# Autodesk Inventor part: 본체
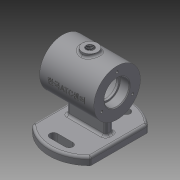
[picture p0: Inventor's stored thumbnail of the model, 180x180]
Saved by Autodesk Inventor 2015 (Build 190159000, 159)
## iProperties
Created: 2021-09
Part Number: 본체
Material: 일반
Document SubType Name: Modeling
Designer: 1019876
Density: 1 g/cm^3
Appearance: 기본값
Author: 1019876
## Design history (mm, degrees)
sketch "스케치1"
  geometry: C1 r 52.5 at (0, 0); 1 further point
  constraints: 1 centre point, 1 coincident
  dimensions: "d0" = 105 diameter of C1
extrude "돌출1" new body sketch "스케치1" distance "d1" = 10; taper "d2" = 0 deg
sketch "스케치2"
  geometry: L1 (-37.5, 36.742)-(-37.5, -36.742); L2 (37.5, 36.742)-(37.5, -36.742); A1 r 52.5 centre (0, 0) between (-37.5, 36.742) and (-37.5, -36.742) reference
  constraints: 4 end point, 4 point on circle, 2 vertical
  dimensions: "d3" = 75 distance between parallel lines of L2 L1; "d4" = 37.5 distance from line of A1.centre L1
extrude "돌출2" cut sketch "스케치2" stored distance "d5" = 10; taper "d6" = 0 deg
sketch "스케치3"
  geometry: L1 (-15, 37)-(15, 37); L2 (-10, 32)-(10, 32); L3 (10, 42)-(-10, 42); A1 r 52.5 centre (0, 0) between (-37.5, -36.742) and (37.5, -36.742) reference; A2 r 5 centre (-10, 37) between (-10, 42) and (-10, 32); A3 r 5 centre (10, 37) between (10, 32) and (10, 42); 1 further point
  constraints: 8 end point, 6 point on circle, 4 tangent, 2 centre point, 2 point on line, 1 horizontal, 1 midpoint, 1 parallel, 1 vertical alignment
  dimensions: "d7" = 20 distance of A3.centre A2.centre; "d8" = 5 distance from line of point (0, 37) L3; "d9" = 37 distance of A1.centre point (0, 37)
extrude "돌출3" cut sketch "스케치3" stored distance "d10" = 10; taper "d11" = 0 deg
sketch "스케치4"
  geometry: L1 (-37.5, 36.742)-(-37.5, -36.742) reference; L2 (-25, 5)-(25, 5); L3 (25, 5)-(25, -5); L4 (25, -5)-(-25, -5); L5 (-25, -5)-(-25, 5); A1 r 52.5 centre (0, 0) between (-37.5, -36.742) and (37.5, -36.742) reference
  constraints: 8 end point, 2 parallel, 1 horizontal, 1 perpendicular
  dimensions: "d12" = 50 distance of L3.end L4.end; "d13" = 12.5 distance between parallel lines of L5 L1; "d14" = 10 distance between parallel lines of L4 L2; "d15" = 5 distance from line of L2 A1.centre
extrude "돌출4" join sketch "스케치4" distance "d16" = 52; taper "d17" = 0 deg
sketch "스케치5"
  geometry: L1 (35, 92)-(-35, 92); L2 (-35, 92)-(-35, 62); L3 (-35, 62)-(35, 62); L4 (35, 62)-(35, 92); L5 (25, 62)-(-25, 62) reference; L6 (-37.5, 0)-(37.5, 0) reference; 3 further points
  constraints: 8 end point, 2 midpoint, 2 parallel, 1 horizontal, 1 perpendicular, 1 vertical alignment
  dimensions: "d18" = 30 distance of L3.end L1.start; "d19" = 0 distance between parallel lines of L5 L3; "d20" = 70 distance of L1.start L1.end
revolve "회전1" sketch "스케치5" stored, may be unused: angle "d21" = 90 deg
sketch "스케치6"
  geometry: C1 r 30 at (0, 0) reference; C2 r 16 at (0, 0); 1 further point
  constraints: 1 centre point, 1 coincident
  dimensions: "d22" = 32 diameter of C2
extrude "돌출5" cut sketch "스케치6" distance "d23" = 12; taper "d24" = 0 deg
sketch "스케치7"
  geometry: C1 r 16 at (0, 0) reference; C2 r 14 at (0, 0); 1 further point
  constraints: 1 centre point, 1 coincident
  dimensions: "d25" = 28 diameter of C2
extrude "돌출6" cut sketch "스케치7" distance "d26" = 3; taper "d27" = 0 deg
sketch "스케치11"
  geometry: C1 r 30 at (0, 0) reference; C2 r 16 at (0, 0); 1 further point
  constraints: 1 centre point, 1 coincident
  dimensions: "d39" = 32 diameter of C2
extrude "돌출10" cut sketch "스케치11" distance "d40" = 12; taper "d41" = 0 deg
sketch "스케치12"
  geometry: C1 r 16 at (0, 0) reference; C2 r 14 at (0, 0); 1 further point
  constraints: 1 centre point, 1 coincident
  dimensions: "d42" = 28 diameter of C2
extrude "돌출11" cut sketch "스케치12" distance "d43" = 3; taper "d44" = 0 deg
sketch "스케치13"
  geometry: C1 r 14 at (0, 0) reference; C2 r 25 at (0, 0); 1 further point
  constraints: 1 centre point, 1 coincident
  dimensions: "d45" = 50 diameter of C2
extrude "돌출12" cut sketch "스케치13" distance "d46" = 40; taper "d47" = 0 deg
fillet "모깎기3" dims "d48" = 0.3
sketch "스케치14"
  geometry: C1 r 16 at (0, 0) reference; 2 further points
  constraints: 1 horizontal alignment
  dimensions: "d49" = 23 distance of C1.centre point (-23, 0)
hole "구멍1" sketch "스케치14" at (-23, 0) diameter "d50" = 3.242; stored, may be unused: countersink angle "d54" = 90 deg, drill point angle "d56" = 118 deg; dims "d51" = 8, "d52" = 4, "d53" = 2, "d55" = 10
node "작업 평면1"
sketch "스케치15"
  geometry: C1 r 10 at (0, 0); 1 further point
  constraints: 1 centre point, 1 coincident
  dimensions: "d61" = 20 diameter of C1
extrude "돌출13" join sketch "스케치15" stored distance "d62" = 40; taper "d63" = 0 deg
sketch "스케치16"
  geometry: C1 r 10 at (0, 0) reference
hole "구멍2" sketch "스케치16" at (0, 0) diameter "d64" = 10.106; stored, may be unused: countersink angle "d68" = 90 deg, drill point angle "d70" = 118 deg; dims "d65" = 24, "d66" = 4, "d67" = 2, "d69" = 30
node "작업 평면2"
sketch "스케치17"
  geometry: L1 (35, -30)-(-35, -30) reference; L2 (-35, 30)-(-35, -30) reference; L3 (35, 30)-(-35, 30) reference; L4 (35, 30)-(35, -30) reference; 2 further points
  constraints: 1 other
  dimensions: "d71" = 30 distance from line of point (0, 0) L3; "d72" = 35 distance from line of point (0, 0) L2
feature "엠보싱1" sketch "스케치17" dims "d7" = 20, "d8" = 5, "d9" = 37, "d73" = 0.5, "d74" = 0
chamfer "모따기1" distance "d75" = 1; stored, may be unused: second distance "d76" = 2, angle "d77" = 45 deg
fillet "모깎기4" dims "d78" = 3
fillet "모깎기5" dims "d79" = 3
fillet "모깎기6" dims "d80" = 3
fillet "모깎기7" dims "d81" = 3
fillet "모깎기8" dims "d82" = 3
fillet "모깎기9" dims "d83" = 3
node "솔리드1"
mirror "대칭1"
pattern_circular "원형 패턴1" dims angle "d58" = 360 deg
mirror "대칭2"
other parameters: "d60" = 95
